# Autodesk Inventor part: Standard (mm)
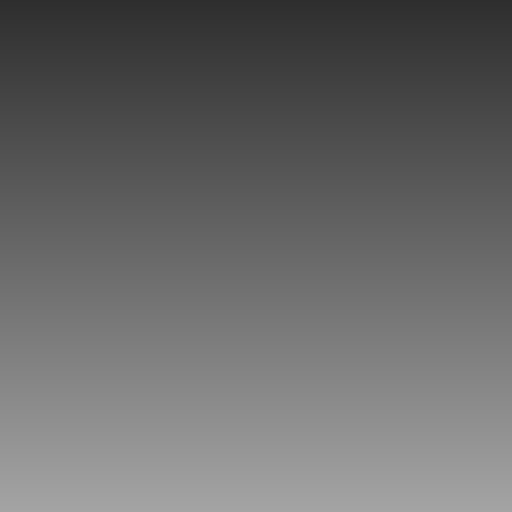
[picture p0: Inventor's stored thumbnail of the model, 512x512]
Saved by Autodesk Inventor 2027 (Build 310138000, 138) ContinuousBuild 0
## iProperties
Shininess: 64.0
Length Units: 11269
Angle Units: 11279
Time Units: 11290
Mass Units: 11283
Length Display Precision: 3
Angle Display Precision: 2
Compacted: True
Part Number: Standard (mm)
Document SubType Name: Modeling
Created: 2002-07
Density: 1 g/cm^3
Material: Generic
Appearance: Default
Density: 0.0
Volumn: 0.0
Area: 0.0
PropertySet Name: Model Information
Control State: 0
Master: False
Checked Out: False
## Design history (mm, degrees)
